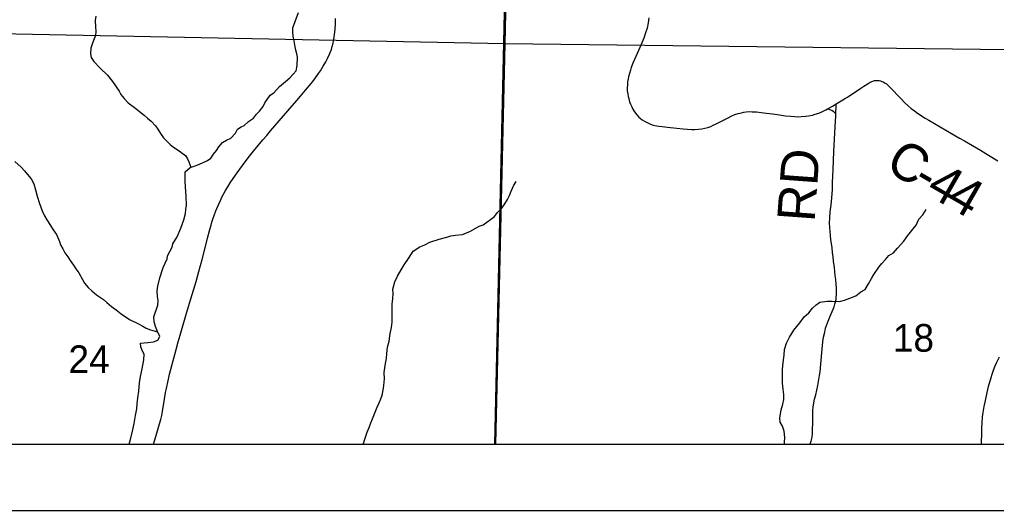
# Model space of a CAD drawing. Extents: x -7.1 to 34, y 0 to 22.
# Drawn here: x 5.914 to 7.392, y 14 to 14.742 of the extents above; entities that cross this region are included whole.
import ezdxf

# ---------------------------------------------------------------- set-up
doc = ezdxf.new("R2010")
doc.units = 0
for name, color, linetype in [('GM_X_County_Road', 7, 'Continuous'), ('GM_X_County_Road_Text', 7, 'Continuous'), ('GM_X_Minor_River', 7, 'Continuous'), ('GM_X_Section', 7, 'Continuous'), ('GM_X_Section_Text', 7, 'Continuous'), ('GM_X_Township_Road', 7, 'Continuous'), ('GM_X_Township_Road_Text', 7, 'Continuous'), ('GM_X_Unincorporated', 7, 'Continuous'), ('SH_Cut_Line', 7, 'Continuous'), ('SH_Data', 7, 'Continuous')]:
    doc.layers.add(name, color=color, linetype=linetype)

msp = doc.modelspace()

# ---------------------------------------------------------------- linework, layer by layer
at = {"layer": 'GM_X_County_Road'}
for points in [[(6.1169, 14.1), (6.1218, 14.117), (6.1259, 14.1308), (6.1278, 14.1376), (6.1293, 14.1433), (6.13, 14.1464), (6.1316, 14.156), (6.1328, 14.1645), (6.1352, 14.1783), (6.136, 14.1824), (6.1395, 14.1984), (6.1413, 14.2059), (6.149, 14.2357), (6.1512, 14.2434), (6.1544, 14.255), (6.1571, 14.2651), (6.1656, 14.2946), (6.1712, 14.3132), (6.1812, 14.3463), (6.1854, 14.3613), (6.1903, 14.3793), (6.1943, 14.3948), (6.1987, 14.4115), (6.2022, 14.4246), (6.2041, 14.4312), (6.2053, 14.4356), (6.2072, 14.4416), (6.2088, 14.446), (6.2112, 14.4527), (6.2126, 14.4563), (6.215, 14.4622), (6.218, 14.4686), (6.2205, 14.4737), (6.2258, 14.4838), (6.2291, 14.4893), (6.233, 14.4955), (6.2375, 14.5019), (6.2435, 14.5104), (6.2557, 14.527), (6.2623, 14.5355), (6.2683, 14.5433), (6.275, 14.5515), (6.2825, 14.5602), (6.2881, 14.5668), (6.2941, 14.5738), (6.3201, 14.6041), (6.3338, 14.6198), (6.3391, 14.6262), (6.3469, 14.6353), (6.3552, 14.6452), (6.3577, 14.6484), (6.3622, 14.6542), (6.3666, 14.6605), (6.3694, 14.6646), (6.3736, 14.6714), (6.3777, 14.6784), (6.3801, 14.683), (6.3833, 14.6896), (6.3843, 14.6921), (6.386, 14.6967), (6.3873, 14.7011), (6.3887, 14.7066), (6.3898, 14.7125), (6.3908, 14.7197), (6.3915, 14.7272), (6.392, 14.7368), (6.3922, 14.7438)], [(6.8663, 14.7448), (6.865, 14.7371), (6.8634, 14.7292), (6.8611, 14.7219), (6.8586, 14.7137), (6.8545, 14.7043), (6.8464, 14.6863), (6.842, 14.6761), (6.8395, 14.6694), (6.8382, 14.6654), (6.8353, 14.6554), (6.8347, 14.6523), (6.834, 14.6477), (6.8337, 14.6433), (6.8335, 14.6387), (6.8336, 14.6343), (6.8342, 14.63), (6.8349, 14.6259), (6.8357, 14.6227), (6.8371, 14.6178), (6.8385, 14.614), (6.8402, 14.61), (6.8421, 14.6064), (6.8436, 14.6039), (6.8461, 14.6004), (6.8485, 14.5973), (6.8511, 14.5946), (6.8536, 14.5924), (6.8561, 14.5906), (6.8597, 14.5884), (6.8637, 14.5863), (6.8676, 14.5845), (6.8714, 14.5831), (6.8754, 14.5819), (6.8814, 14.5808), (6.8862, 14.5802), (6.8943, 14.5794), (6.9084, 14.5778), (6.9182, 14.577), (6.9244, 14.5765), (6.9305, 14.5761), (6.9355, 14.5761), (6.9412, 14.5764), (6.9464, 14.577), (6.9508, 14.5777), (6.9555, 14.5791), (6.96, 14.5806), (6.9636, 14.5822), (6.9671, 14.584), (6.9851, 14.5931), (6.9917, 14.5963), (6.9962, 14.5984), (7.0011, 14.6), (7.0062, 14.6013), (7.0101, 14.6022), (7.0136, 14.6027), (7.0177, 14.6029), (7.0227, 14.6027), (7.0291, 14.6024), (7.0361, 14.6017), (7.0439, 14.6008), (7.0533, 14.5995), (7.0636, 14.5979), (7.0729, 14.5966), (7.0809, 14.5958), (7.0869, 14.5954), (7.0923, 14.5952), (7.0964, 14.5953), (7.1029, 14.5958), (7.1078, 14.5965), (7.1135, 14.5977), (7.1178, 14.5989), (7.1233, 14.6008), (7.1269, 14.6023), (7.134, 14.6057), (7.1364, 14.607), (7.1394, 14.6086), (7.144, 14.6112), (7.1497, 14.6145), (7.162, 14.622), (7.1668, 14.6249), (7.1866, 14.6383), (7.1913, 14.6415), (7.198, 14.6456), (7.2008, 14.6472), (7.205, 14.6491), (7.2077, 14.6499), (7.2108, 14.6502), (7.2148, 14.6498), (7.2168, 14.6493), (7.2188, 14.6486), (7.2206, 14.6478), (7.2237, 14.6461), (7.2256, 14.6447), (7.2288, 14.6418), (7.2314, 14.6393), (7.2473, 14.6225), (7.2533, 14.6163), (7.2584, 14.6118), (7.2631, 14.6077), (7.2679, 14.604), (7.2728, 14.6005), (7.2844, 14.593), (7.2896, 14.5898), (7.3241, 14.5699), (7.3361, 14.5629), (7.3435, 14.5587), (7.3678, 14.5445), (7.3801, 14.5371), (7.3939, 14.5287)]]:
    msp.add_lwpolyline(points, dxfattribs=at)
at = {"layer": 'GM_X_Minor_River'}
msp.add_line((6.6622, 14.4917), (6.6655, 14.4974), dxfattribs=at)
for points in [[(6.331, 14.739), (6.3361, 14.7527)], [(6.0295, 14.747), (6.0289, 14.7405), (6.029, 14.731), (6.0295, 14.7241), (6.0292, 14.718), (6.0274, 14.7127), (6.0248, 14.7062), (6.0223, 14.6989), (6.0217, 14.6905), (6.0225, 14.6848), (6.0264, 14.6788), (6.0364, 14.6687), (6.0475, 14.6578), (6.0548, 14.6484), (6.0649, 14.6337), (6.0676, 14.6288), (6.0723, 14.6228), (6.0788, 14.616), (6.0883, 14.6093), (6.0956, 14.6033), (6.1029, 14.5977), (6.1079, 14.5928), (6.1133, 14.5887), (6.1198, 14.5816), (6.1233, 14.5763), (6.1275, 14.5699), (6.1322, 14.5635), (6.1422, 14.553), (6.1472, 14.5493), (6.1556, 14.5437), (6.1605, 14.54), (6.1655, 14.5366), (6.1682, 14.5317), (6.1706, 14.5268), (6.1732, 14.5187)], [(6.0799, 14.1), (6.082, 14.1072), (6.0853, 14.1198), (6.0877, 14.1316), (6.0898, 14.1435), (6.0916, 14.1538), (6.0922, 14.1614), (6.0932, 14.1701), (6.0946, 14.1804), (6.0956, 14.193), (6.0973, 14.2026), (6.0998, 14.214), (6.1022, 14.2278), (6.1029, 14.2361), (6.0998, 14.2418), (6.0978, 14.2475), (6.097, 14.2528), (6.1083, 14.2541), (6.117, 14.255), (6.1234, 14.2574), (6.1263, 14.2631), (6.1228, 14.2703), (6.1197, 14.2779), (6.1181, 14.2851), (6.1176, 14.2927), (6.1194, 14.2988), (6.1216, 14.3042), (6.1234, 14.3103), (6.124, 14.3175), (6.1228, 14.3232), (6.1227, 14.332), (6.1233, 14.3392), (6.1266, 14.3514), (6.1313, 14.3675), (6.1375, 14.3802), (6.1382, 14.3851), (6.1452, 14.3982), (6.1459, 14.4031), (6.1525, 14.4135), (6.1584, 14.4265), (6.1628, 14.4391), (6.1653, 14.4491), (6.1659, 14.4548), (6.1666, 14.4613), (6.1664, 14.4746), (6.1654, 14.4891), (6.1649, 14.4978), (6.1647, 14.5119), (6.1726, 14.5185), (6.1786, 14.5205), (6.1839, 14.5224), (6.191, 14.5256), (6.1986, 14.5291), (6.2038, 14.5326), (6.2075, 14.5384), (6.212, 14.5442), (6.2157, 14.5496), (6.2213, 14.5561), (6.2273, 14.56), (6.234, 14.5628), (6.2407, 14.5701), (6.2441, 14.5763), (6.2493, 14.5798), (6.2542, 14.5821), (6.2605, 14.5879), (6.268, 14.593), (6.2725, 14.5991), (6.2774, 14.6038), (6.2826, 14.6107), (6.2851, 14.6161), (6.2933, 14.628), (6.2989, 14.6311), (6.3075, 14.6408), (6.3165, 14.6485), (6.3232, 14.654), (6.328, 14.6594), (6.3325, 14.6644), (6.3343, 14.6728), (6.3345, 14.6853), (6.3336, 14.6903), (6.3324, 14.696), (6.3312, 14.7009), (6.3299, 14.71), (6.3283, 14.7172), (6.3275, 14.7237), (6.3278, 14.7298), (6.331, 14.739)], [(5.9071, 14.5274), (5.9166, 14.5188), (5.922, 14.5132), (5.9263, 14.5079), (5.9317, 14.5015), (5.9359, 14.4936), (5.9383, 14.4849), (5.9411, 14.475), (5.9447, 14.464), (5.9487, 14.453), (5.9522, 14.4455), (5.9557, 14.4391), (5.9611, 14.4308), (5.9653, 14.4244), (5.97, 14.4172), (5.9747, 14.4066), (5.9763, 14.4017), (5.9798, 14.3953), (5.9829, 14.3896), (5.9875, 14.3832), (5.991, 14.3779), (5.996, 14.3708), (5.9995, 14.3655), (6.0038, 14.3591), (6.0096, 14.3493), (6.0123, 14.3436), (6.0181, 14.3372), (6.0235, 14.332), (6.0308, 14.326), (6.0411, 14.3189), (6.0465, 14.3145), (6.0534, 14.3085), (6.0603, 14.3032), (6.0679, 14.2973), (6.0759, 14.2917), (6.0817, 14.288), (6.0931, 14.2824), (6.1008, 14.2784), (6.1057, 14.2754), (6.1122, 14.2732), (6.1179, 14.2714), (6.123, 14.2699)], [(6.1687, 14.5293), (6.1686, 14.5294)], [(6.434, 14.1), (6.4346, 14.1011), (6.4364, 14.108), (6.4401, 14.1183), (6.443, 14.1256), (6.4455, 14.1325), (6.4481, 14.1386), (6.4514, 14.1463), (6.4554, 14.1562), (6.4583, 14.1628), (6.4609, 14.1685), (6.4627, 14.1742), (6.4645, 14.1819), (6.4655, 14.1891), (6.4661, 14.199), (6.466, 14.2085), (6.4667, 14.2154), (6.4677, 14.2223), (6.4691, 14.2299), (6.4701, 14.2372), (6.4711, 14.2467), (6.4733, 14.2559), (6.475, 14.2677), (6.4771, 14.2765), (6.4778, 14.2845), (6.4781, 14.2902), (6.4779, 14.2978), (6.4781, 14.3119), (6.4791, 14.3206), (6.4794, 14.3275), (6.4789, 14.3343), (6.4822, 14.3454), (6.4862, 14.3542), (6.4914, 14.3635), (6.4962, 14.3715), (6.5025, 14.3808), (6.5099, 14.3919), (6.52, 14.3985), (6.5275, 14.4017), (6.5351, 14.4056), (6.549, 14.41), (6.5607, 14.4132), (6.5667, 14.4152), (6.5735, 14.4161), (6.5841, 14.417), (6.5962, 14.4221), (6.6097, 14.4296), (6.6157, 14.432), (6.6269, 14.4397), (6.6329, 14.4444), (6.637, 14.4506), (6.6437, 14.4571), (6.6482, 14.4637), (6.6522, 14.4702), (6.6556, 14.476), (6.6581, 14.4829), (6.6622, 14.4917)], [(7.0712, 14.1), (7.0714, 14.1025), (7.0717, 14.1101), (7.0708, 14.12), (7.0681, 14.1272), (7.0649, 14.1336), (7.0641, 14.1397), (7.0662, 14.1523), (7.0691, 14.1607), (7.0705, 14.1679), (7.0704, 14.1755), (7.0695, 14.1835), (7.0682, 14.1923), (7.0681, 14.2044), (7.0683, 14.2132), (7.0693, 14.2239), (7.0707, 14.2345), (7.0713, 14.2433), (7.0742, 14.2529), (7.079, 14.2617), (7.0856, 14.2725), (7.0945, 14.2836), (7.1012, 14.2929), (7.108, 14.2987), (7.1135, 14.3056), (7.1191, 14.3106), (7.1248, 14.3149), (7.1361, 14.3166), (7.1433, 14.3163), (7.1547, 14.3161), (7.1622, 14.3178), (7.1701, 14.3209), (7.1795, 14.3245), (7.187, 14.3303), (7.1934, 14.3342), (7.1986, 14.3427), (7.203, 14.3504), (7.2067, 14.3565), (7.2141, 14.3677), (7.2186, 14.3734), (7.2241, 14.3796), (7.229, 14.3854), (7.2365, 14.3893), (7.2425, 14.3963), (7.2521, 14.4071), (7.2581, 14.4155), (7.2659, 14.4256), (7.2703, 14.4313), (7.2748, 14.4405), (7.2807, 14.4471), (7.2855, 14.4548)]]:
    msp.add_lwpolyline(points, dxfattribs=at)
at = {"layer": 'GM_X_Section'}
for points in [[(6.6705, 15.7268), (6.6482, 14.7054), (5.6272, 14.7254), (5.6569, 15.7356)], [(7.6901, 15.7003), (7.6641, 14.6933), (6.6482, 14.7054), (6.6705, 15.7268)]]:
    msp.add_lwpolyline(points, close=True, dxfattribs=at)
at = {"layer": 'GM_X_Township_Road'}
for points in [[(2.1, 17.7253), (2.1, 14.1), (6.633, 14.1), (6.6565, 15.1357), (6.6586, 15.2372), (6.6748, 15.9993), (6.6822, 16.3488), (6.7058, 17.2839), (6.7118, 17.7486)], [(7.1098, 14.1), (7.11, 14.1006), (7.1116, 14.1049), (7.1126, 14.109), (7.1135, 14.1147), (7.1137, 14.1193), (7.114, 14.1349), (7.1143, 14.1458), (7.1144, 14.151), (7.1149, 14.1563), (7.1158, 14.1629), (7.117, 14.1681), (7.1186, 14.1749), (7.1219, 14.1891), (7.1229, 14.1948), (7.1245, 14.2038), (7.1251, 14.2096), (7.1272, 14.2328), (7.1294, 14.2547), (7.1306, 14.2622), (7.1322, 14.2697), (7.1336, 14.2756), (7.1363, 14.2834), (7.1403, 14.2939), (7.1463, 14.3078), (7.1476, 14.3118), (7.1487, 14.3155), (7.1493, 14.319), (7.1497, 14.3226), (7.15, 14.3261), (7.1498, 14.3363), (7.1494, 14.3422), (7.1488, 14.3491), (7.1482, 14.3553), (7.1469, 14.3674), (7.1457, 14.3769), (7.1449, 14.3836), (7.1441, 14.3901), (7.1433, 14.3969), (7.1425, 14.4033), (7.1417, 14.4093), (7.141, 14.4154), (7.1404, 14.4217), (7.1399, 14.4277), (7.1396, 14.435), (7.1398, 14.4418), (7.1407, 14.4516), (7.1418, 14.4621), (7.1428, 14.4725), (7.1438, 14.4853), (7.1441, 14.4958), (7.1446, 14.5053), (7.1451, 14.5156), (7.1461, 14.5426), (7.1473, 14.571), (7.1485, 14.5887), (7.1488, 14.5962), (7.1489, 14.5995), (7.1491, 14.6038), (7.1494, 14.6083), (7.1497, 14.6145)], [(7.1364, 14.607), (7.1382, 14.6065), (7.1408, 14.6058), (7.1432, 14.6049), (7.145, 14.6038), (7.1467, 14.6023), (7.1489, 14.5995)], [(7.3693, 14.1), (7.3696, 14.1041), (7.3699, 14.1149), (7.3701, 14.1237), (7.3705, 14.1327), (7.3709, 14.1413), (7.3717, 14.1481), (7.3734, 14.157), (7.3749, 14.1635), (7.3781, 14.1783), (7.38, 14.1873), (7.3839, 14.2011), (7.3855, 14.2062), (7.3875, 14.212), (7.3899, 14.2184), (7.3919, 14.2231), (7.3965, 14.2324)]]:
    msp.add_lwpolyline(points, dxfattribs=at)
msp.add_lwpolyline([(6.633, 14.1), (8.9, 14.1), (8.9, 17.7079), (8.6668, 17.7136), (8.4472, 17.7189), (7.7202, 17.7285), (6.7118, 17.7486), (6.7058, 17.2839), (6.6822, 16.3488), (6.6748, 15.9993), (6.6586, 15.2372), (6.6565, 15.1357)], close=True, dxfattribs=at)
at = {"layer": 'GM_X_Unincorporated'}
for points in [[(5.6136, 14.1), (6.6341, 14.1), (6.6482, 14.7054), (5.6272, 14.7254)], [(6.6341, 14.1), (7.6503, 14.1), (7.6641, 14.6933), (6.6482, 14.7054)]]:
    msp.add_lwpolyline(points, close=True, dxfattribs=at)
at = {"layer": 'SH_Cut_Line'}
msp.add_lwpolyline([(2.1, 17.7253), (2.1, 14.1), (8.9, 14.1), (8.9, 17.7079), (8.6668, 17.7136), (8.4472, 17.7189), (7.7202, 17.7285), (6.7118, 17.7486), (6.3575, 17.7557), (6.1904, 17.7592), (5.7514, 17.7685), (5.5047, 17.7737), (5.1115, 17.7819), (5.0544, 17.7831), (5.0443, 17.7832), (4.7094, 17.7848), (4.5657, 17.7857), (4.3, 17.7873), (3.8304, 17.7952), (3.8238, 17.6717), (3.7215, 17.6707), (3.0659, 17.6986), (2.7886, 17.7105), (2.5551, 17.7155)], close=True, dxfattribs=at)
at = {"layer": 'SH_Data'}
for p, q in [((2.1, 14.1), (8.9, 14.1)), ((2, 14), (9, 14))]:
    msp.add_line(p, q, dxfattribs=at)

# ---------------------------------------------------------------- texts
at = {"layer": 'GM_X_County_Road_Text'}
for s, rotation, p in [('C', 327.8039, (7.2214, 14.5169)), ('4', 330.1168, (7.2832, 14.479)), ('-', 329.9361, (7.2628, 14.4908)), ('4', 330.2074, (7.3136, 14.4616))]:
    msp.add_text(s, height=0.0568, rotation=rotation, dxfattribs=at).set_placement(p)
at = {"layer": 'GM_X_Section_Text'}
for s, p in [('18', (7.2353, 14.2399)), ('24', (5.9883, 14.2077))]:
    msp.add_text(s, height=0.04186, rotation=0, dxfattribs=at).set_placement(p)
at = {"layer": 'GM_X_Township_Road_Text'}
msp.add_text('RD', height=0.05682, rotation=85.814, dxfattribs=at).set_placement((7.1168, 14.4352))

doc.saveas('drawing.dxf')
